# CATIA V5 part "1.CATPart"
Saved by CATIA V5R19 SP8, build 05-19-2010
Part number: 1
Bounding box of the stored display mesh (mm): x -230 to 10, y -16 to 6, z -25 to 25
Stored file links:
  D:\Dropbox\IAO\IAO_2010\iao\IAO Reviser CAO\Problemes\IAO_2010_1447_melguidj\Catia_1447_melguidj\1.CATPart
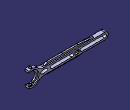
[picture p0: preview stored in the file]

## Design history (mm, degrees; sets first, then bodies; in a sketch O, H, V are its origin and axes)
Parameters
  AE1 = 180 mm
  AD1 = 70 mm
Body1 (main body)
  Sketch1 on zx-plane, origin (0, 0, 0), H (-1, 0, 0), V (0, 0, 1)
    line L1 (35.7071, -10) -> (220, -10)
    line L2 (220, 10) -> (35.7071, 10)
    point P1 (220, -10)
    point P2 (220, 10)
    construction line L3 (150, 0) -> (220, 0)
    point P3 (150, 0)
    line L4 (150, 5) -> (220, 5)
    line L5 (220, -5) -> (150, -5)
    arc A1 centre (220, 0) radius 5 from (220, 5) to (220, -5) cw
    arc A2 centre (150, 0) radius 5 from (150, -5) to (150, 5) cw
    construction line L6 (60, 0) -> (120, 0)
    point P9 (60, 0)
    point P10 (120, 0)
    line L7 (60, 5) -> (120, 5)
    line L8 (120, -5) -> (60, -5)
    arc A3 centre (120, 0) radius 5 from (120, 5) to (120, -5) cw
    arc A4 centre (60, 0) radius 5 from (60, -5) to (60, 5) cw
    arc A5 centre (0, 0) radius 20 from (-10, 17.3205) to (-10, -17.3205) cw
    point P15 (0, 0)
    line L9 (-10, 17.3205) -> (-10, 22.9129)
    point P18 (-10, 22.9129)
    line L10 (-10, -17.3205) -> (-10, -22.9129)
    arc A6 centre (0, 0) radius 25 from (-10, 22.9129) to (17.8536, 17.5) cw
    point P20 (0, 0)
    point P21 (-10, 22.9129)
    point P22 (22.9129, -10)
    arc A7 centre (0, 0) radius 25 from (17.8536, -17.5) to (-10, -22.9129) cw
    construction line L11 (20, 36.6166) -> (20, -39.7535)
    arc A8 centre (220, 0) radius 10 from (220, 10) to (220, -10) cw
    point P25 (220, 0)
    axis line L12 (-10, 39.084) -> (-10, -27.4612)
    reference projected point E1 (0, 0) from Sketch6
    arc A9 centre (35.7071, 35) radius 25 from (17.8536, 17.5) to (35.7071, 10) ccw
    arc A10 centre (35.7071, -35) radius 25 from (17.8536, -17.5) to (35.7071, -10) cw
    distance L3 L4 = 5
    distance L3 L1 = 10
    length L5 = 70
    distance L6 L7 = 5
    length L7 = 60
    distance P10 P3 = 30
    distance L11 A5 = 0
    radius A5 = 20
    distance P1 P2 = 20
    distance A1 A8 = 5
    distance L12 V = 10
    distance L9 P25 = 230
    radius A6 = 25
    radius A9 = 25
    radius A10 = 25
    horizontal: L1 H, L2 H, L3 H, L6 H
    tangency: A1 L4, A2 L4, A1 L5, A2 L5, A3 L7, A4 L7, A3 L8, A4 L8, A8 L1, A8 L2, A9 A6, A9 L2, A10 A7, A10 L1
    coincidence: P9 L3, P15 L6, P21 P18, P20 P15, A6 P22, A6 A7, L6 H, L9 L12, L10 L9, A7 P22, L1 P22
    vertical: L9 V, L10 V, L11 V, L12 V
    concentricity: A5 E1
  Pad1: profile Sketch1, direction (0, 1, 0), length 6, mirrored extent
  Sketch2 on xy-plane, origin (0, 0, 0), H (1, 0, 0), V (0, 1, 0)
    circle A1 centre (0, 0) radius 4
    point P1 (0, 0)
    radius A1 = 4
    coincidence: P1 O
  Pocket1: profile Sketch2, direction (0, 0, -1), through (limit type 3), opposite side through (limit type 3)
  Sketch3 on start face of Pad1, origin (0, -6, 0), H (1, 0, 0), V (0, 0, 1)
    circle A1 centre (-29, 0) radius 4
    point P1 (-29, 0)
    reference projected arc E1 centre (0, 0) radius 20 from (10, 17.3205) to (10, -17.3205) ccw from edge [start face of Pad1 | face of Pad1 from Sketch1.A5]
    radius A1 = 4
    distance A1 E1 = 5
    coincidence: P1 H
  Pad2: profile Sketch3, direction (0, -1, 0), length 10
  Sketch4 on zx-plane, origin (0, 0, 0), H (-1, 0, 0), V (0, 0, 1)
    arc A1 centre (0, 0) radius 15 from (6, -13.7477) to (6, 13.7477) ccw
    point P1 (6, -13.7477)
    point P2 (6, 13.7477)
    construction line L1 (6, 36.7811) -> (6, -37.0173)
    reference projected arc E1 centre (0, 0) radius 20 from (-10, -17.3205) to (-10, 17.3205) ccw from edge [face of Pad1 from Sketch1.A5 | end face of Pad1]
    arc A2 centre (0, 0) radius 20 from (6, -19.0788) to (6, 19.0788) ccw
    point P5 (6, 19.0788)
    point P6 (6, -19.0788)
    reference projected arc E2 centre (0, 0) radius 20 from (-10, -17.3205) to (-10, 17.3205) ccw from edge [face of Pad1 from Sketch1.A5 | end face of Pad1]
    line L2 (6, -19.0788) -> (6, -13.7477)
    line L3 (6, 13.7477) -> (6, 19.0788)
    construction line L4 (232.1602, 0) -> (-35.1645, 0)
    point P7 (232.1602, 0)
    point P9 (41, 10)
    line L5 (41, 10) -> (49.6603, 15)
    point P10 (49.6603, 15)
    line L6 (49.6603, 15) -> (96, 15)
    line L7 (96, 10) -> (41, 10)
    reference projected line E3 (220, 10) -> (35.7071, 10) from edge [face of Pad1 from Sketch1.L2 | end face of Pad1]
    point P11 (49.6603, 15)
    point P12 (49.6603, 15)
    axis line L8 (96, 56.5793) -> (96, -31.7607)
    point P15 (96, 15)
    point P16 (96, 10)
    point P17 (96, 15)
    point P18 (96, 10)
    point P19 (189.9116, 10)
    point P20 (142.3397, 15)
    point P21 (142.3397, 15)
    point P22 (142.3397, 15)
    point P23 (96, 15)
    point P24 (96, 10)
    point P25 (96, 15)
    point P26 (96, 10)
    line L9 (189.9116, 10) -> (142.3397, 15)
    line L10 (142.3397, 15) -> (96, 15)
    line L11 (96, 10) -> (189.9116, 10)
    point P27 (41, -10)
    point P28 (49.6603, -15)
    point P29 (49.6603, -15)
    point P30 (49.6603, -15)
    point P31 (96, -15)
    point P32 (96, -10)
    point P33 (96, -15)
    point P34 (96, -10)
    point P35 (189.9116, -10)
    point P36 (142.3397, -15)
    point P37 (142.3397, -15)
    point P38 (142.3397, -15)
    point P39 (96, -15)
    point P40 (96, -10)
    point P41 (96, -15)
    point P42 (96, -10)
    line L12 (41, -10) -> (49.6603, -15)
    line L13 (49.6603, -15) -> (96, -15)
    line L14 (96, -10) -> (41, -10)
    line L15 (189.9116, -10) -> (142.3397, -15)
    line L16 (142.3397, -15) -> (96, -15)
    line L17 (96, -10) -> (189.9116, -10)
    reference projected line E4 (220, 10) -> (35.7071, 10) from edge [face of Pad1 from Sketch1.L2 | end face of Pad1]
    distance L1 V = 6
    radius A1 = 15
    distance L6 L7 = 5
    angle L5 L7 = 30
    distance P9 L1 = 35
    distance L8 P9 = 55
    angle L11 L9 = 6
    vertical: L1 V, L2 V, L3 V, L8 V
    coincidence: L1 P2, P1 L1, P5 L1, P6 L1, A2 E2, P7 H, L7 E3, L6 P12, L5 P10, L8 P15, L8 P16, P11 P10, P16 P24, P15 P23, P20 P21, P28 P29, P31 P39, P32 P40, P36 P37, L11 E4
    concentricity: A1 E1
    horizontal: L6 H, L7 H
    symmetry: P10 P20 L8, P11 P21 L8, P15 P23 L8, P16 P24 L8, P9 P27 L4, P10 P28 L4, P11 P29 L4, P12 P30 L4, P15 P31 L4, P16 P32 L4, P17 P33 L4, P18 P34 L4, P19 P35 L4, P20 P36 L4, P21 P37 L4, P22 P38 L4, P23 P39 L4, P24 P40 L4, P25 P41 L4, P26 P42 L4, L5 L12 L4, L6 L13 L4, L7 L14 L4, L9 L15 L4, L10 L16 L4, L11 L17 L4
  Pad3: profile Sketch4, direction (0, 1, 0), length 2.5, mirrored extent
  Fillet1: radius 2, on edge [face of Pad3 from Sketch4.L3 | face of Pad1 from Sketch1.A5]
  Fillet2: radius 2, on edge [face of Pad1 from Sketch1.A5 | face of Pad3 from Sketch4.L2]
  Fillet3: radius 3, on edge [face of Pad1 from Sketch1.L2 | face of Pad3 from Sketch4.L5]; edge [face of Pad3 from Sketch4.L5 | face of Pad3 from Sketch4.L6]
  Fillet4: radius 3, on edge [face of Pad3 from Sketch4.L9 | face of Pad1 from Sketch1.L2]; edge [face of Pad3 from Sketch4.L10 | face of Pad3 from Sketch4.L9]; edge [face of Pad1 from Sketch1.L1 | face of Pad3 from Sketch4.L15]; edge [face of Pad3 from Sketch4.L15 | face of Pad3 from Sketch4.L16]; edge [face of Pad3 from Sketch4.L13 | face of Pad3 from Sketch4.L12]; edge [face of Pad3 from Sketch4.L12 | face of Pad1 from Sketch1.L1]
  Fillet5: radius 4, on edge [face of Pad3 from Sketch4.L2 | face of Pad3 from Sketch4.A1]; edge [face of Pad3 from Sketch4.A1 | face of Pad3 from Sketch4.L3]
  Sketch5 on end face of Pad1, origin (0, 6, 0), H (-1, 0, 0), V (0, 0, 1)
    construction line L1 (253.4328, 0) -> (-63.0915, 0)
    point P1 (253.4328, 0)
    spline S1 through (24.0575, 0) (31.4268, 4.5069) (47.5777, 0)
    point P3 (129, 5)
    line L2 (131, 5) -> (139, 5)
    line L3 (141, 3) -> (141, 0)
    line L4 (129, 0) -> (129, 3)
    point P4 (141, 5)
    point P5 (141, 0)
    point P6 (129, 0)
    reference projected line E1 (120, 5) -> (60, 5) from edge [end face of Pad1 | face of Pad1 from Sketch1.L7]
    spline S2 through (24.0575, 0) (31.4268, -4.5069) (47.5777, 0)
    point P7 (129, -5)
    point P8 (129, 0)
    line L5 (129, 0) -> (129, -3)
    point P9 (141, -5)
    line L6 (131, -5) -> (139, -5)
    point P10 (141, 0)
    line L7 (141, -3) -> (141, 0)
    axis line L8 (135, 24.944) -> (135, -24.0978)
    reference projected point E2 (150, 0) from axis of face of Pad1 from Sketch1.A2
    arc A1 centre (131, 3) radius 2 from (129, 3) to (131, 5) cw
    arc A2 centre (139, 3) radius 2 from (139, 5) to (141, 3) cw
    arc A3 centre (139, -3) radius 2 from (139, -5) to (141, -3) ccw
    arc A4 centre (131, -3) radius 2 from (131, -5) to (129, -3) cw
    point P25 (24.0575, 0)
    point P26 (47.5777, 0)
    point P27 (47.5777, 0)
    point P28 (24.0575, 0)
    point P29 (31.4268, 4.5069)
    point P30 (31.4268, -4.5069)
    distance L2 E1 = 0
    distance L8 E2 = 15
    distance L3 L8 = 6
    distance L4 L8 = 6
    radius A1 = 2
    radius A2 = 2
    radius A3 = 2
    radius A4 = 2
    coincidence: P1 H, P25 L1, P26 L1, P5 L1, P25 P28, P26 P27, P5 P10, P6 P8, L4 P3, L2 P3, L2 P4, L3 P4, L6 P9, L7 P9, L6 P7, L5 P7
    horizontal: L1 H, L2 H
    vertical: L3 V, L4 V, L8 V
    symmetry: S1 S2 L1, P3 P7 L1, P6 P8 L1, L4 L5 L1, P4 P9 L1, L2 L6 L1, P5 P10 L1, L3 L7 L1, P26 P27 L1, P25 P28 L1, P29 P30 L1
    tangency: A1 L4, A1 L2, A2 L2, A2 L3, A3 L6, A3 L7, A4 L6, A4 L5
  Pocket2: profile Sketch5, direction (0, -1, 0), through (limit type 6)
  Sketch6, origin (7.4637, -11, -2.8797), H (-0.933, 0, 0.36), V (0.36, 0, 0.933), geometry linked from another document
